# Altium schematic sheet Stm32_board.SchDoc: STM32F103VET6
size C; Organization: Protel International P/L; Address1: L3, 12a Rodborough Rd; Address2: Frenchs Forest; Address3: NSW; Address4: Australia 2086; DocumentNumber: yangjing; Revision: V1.0; SheetNumber: 0; SheetTotal: 0
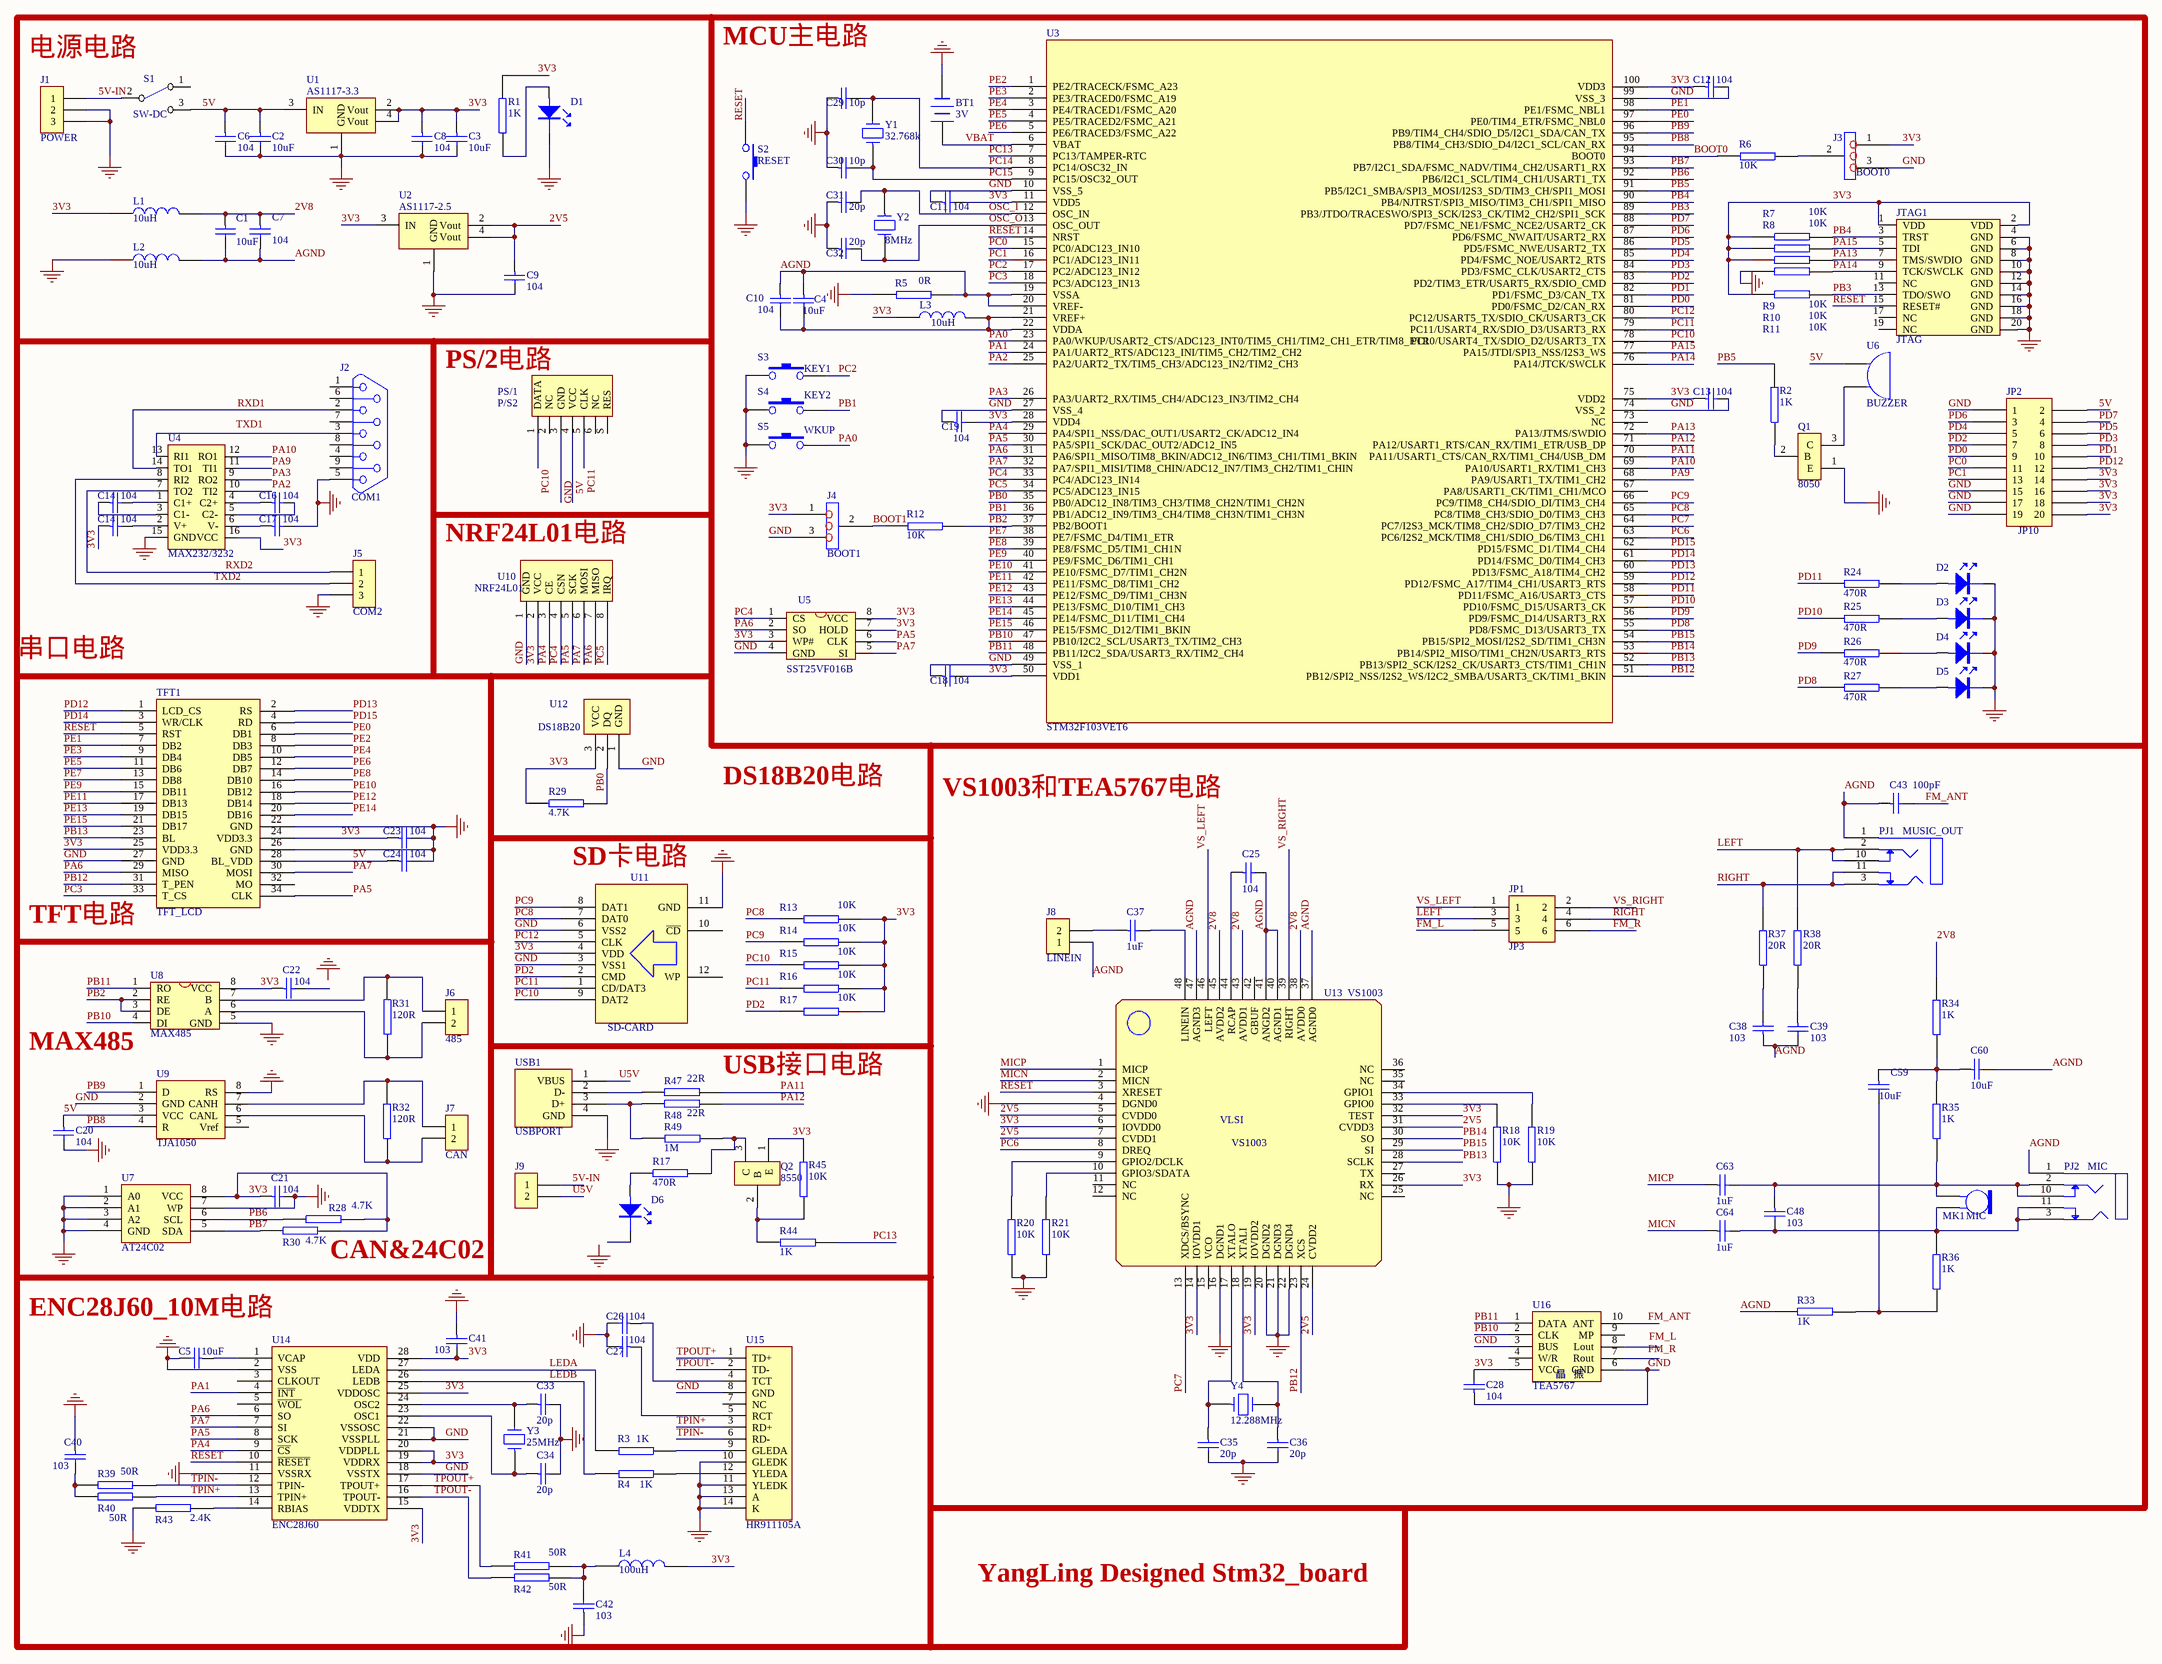
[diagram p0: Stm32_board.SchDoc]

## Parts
(Parts that share a designator on the sheet are numbered #1, #2 ... from top to bottom, then left to right.)
BT1  3V  [BAT600]
C1  10uF  [0805C]
C2  10uF  [0805C]
C3  10uF  [0805C]
C4  10uF  [0805C]
C5  10uF  [0805C]
C6  104  [0805C]
C7  104  [0805C]
C8  104  [0805C]
C9  104  [0805C]
C10  104  [0805C]
C11  104  [0805C]
C12  104  [0805C]
C13  104  [0805C]
C14#1  104  [0805C]
C14#2  104  [0805C]
C16  104  [0805C]
C17  104  [0805C]
C18  104  [0805C]
C19  104  [0805C]
C20  104  [0805C]
C21  104  [0805C]
C22  104  [0805C]
C23  104  [0805C]
C24  104  [0805C]
C25  104  [0805C]
C26  104  [0805C]
C27  104  [0805C]
C28  104  [0805C]
C29  10p  [0805C]
C30  10p  [0805C]
C31  20p  [0805C]
C32  20p  [0805C]
C33  20p  [0805C]
C34  20p  [0805C]
C35  20p  [0805C]
C36  20p  [0805C]
C37  1uF  [0805C]
C38  103  [0805C]
C39  103  [0805C]
C40  103  [0805C]
C41  103  [0805C]
C42  103  [0805C]
C43  100pF  [0805C]
C48  103  [0805C]
C59  10uF  [0805C]
C60  10uF  [0805C]
C63  1uF  [0805C]
C64  1uF  [0805C]
D1  LEDD  [0805D]  (value not drawn)
D2  LEDD  [0805D]  (value not drawn)
D3  LEDD  [0805D]  (value not drawn)
D4  LEDD  [0805D]  (value not drawn)
D5  LEDD  [0805D]  (value not drawn)
D6  LEDD  [0805D]  (value not drawn)
J1  POWER  [DC10B]
J2  COM1  [DB9_M]
J3  BOOT0  [SIP_03]
J4  BOOT1  [SIP_03]
J5  COM2  [SIP_03]
J6  485  [DC-2]
J7  CAN  [DC-2]
J8  LINEIN  [SIP_02]
J9  CON2  [SIP_02]  (value not drawn)
JP1  JP3  [JP3]
JP2  JP10  [JP10]
JTAG1  JTAG  [JTAG_20]
L1  10uH  [0805R]
L2  10uH  [0805R]
L3  10uH  [0805R]
L4  100uH  [0805R]
MK1  MIC  [SIP_02]
PJ1  MUSIC_OUT  [PJ-215-B]
PJ2  MIC  [PJ-215-B]
PS/1  P/S2  [PS2-6PIN]
Q1  8050  [SOT-23]
Q2  8550  [SOT-23]
R1  1K  [0805R]
R2  1K  [0805R]
R3  1K  [0805R]
R4  1K  [0805R]
R5  0R  [0805R]
R6  10K  [0805R]
R7  10K  [0805R]
R8  10K  [0805R]
R9  10K  [0805R]
R10  10K  [0805R]
R11  10K  [0805R]
R12  10K  [0805R]
R13  10K  [0805R]
R14  10K  [0805R]
R15  10K  [0805R]
R16  10K  [0805R]
R17#1  10K  [0805R]
R17#2  470R  [0805R]
R18  10K  [0805R]
R19  10K  [0805R]
R20  10K  [0805R]
R21  10K  [0805R]
R24  470R  [0805R]
R25  470R  [0805R]
R26  470R  [0805R]
R27  470R  [0805R]
R28  4.7K  [0805R]
R29  4.7K  [0805R]
R30  4.7K  [0805R]
R31  120R  [0805R]
R32  120R  [0805R]
R33  1K  [0805R]
R34  1K  [0805R]
R35  1K  [0805R]
R36  1K  [0805R]
R37  20R  [0805R]
R38  20R  [0805R]
R39  50R  [0805R]
R40  50R  [0805R]
R41  50R  [0805R]
R42  50R  [0805R]
R43  2.4K  [0805R]
R44  1K  [0805R]
R45  10K  [0805R]
R47  22R  [0805R]
R48  22R  [0805R]
R49  1M  [0805R]
S1  SW-DC  [SW-DC]
S2  RESET  [ANJIAN]
S3  KEY1  [ANJIAN]
S4  KEY2  [ANJIAN]
S5  WKUP  [ANJIAN]
TFT1  TFT_LCD  [LCD240320]
U1  AS1117-3.3  [AMS1117]
U2  AS1117-2.5  [ASM1117-2.5V]
U3  STM32F103VET6  [STM32F103VET6]
U4  MAX232/3232  [SOP16_MAX3232]
U5  SST25VF016B  [SOIC-8]
U6  BUZZER  [BEEP]
U7  AT24C02  [SOP-8]
U8  MAX485
U9  TJA1050  [SOP-8]
U10  NRF24L01  [NRF24L01]
U11  SD-CARD  [SDCARD_L]
U12  DS18B20  [DS18B20]
U13  VS1003  [LQFP-48]
U14  ENC28J60  [SSOP28_ENC28J60]
U15  HR911105A  [HR911105A]
U16  TEA5767  [TEA5767]
USB1  USBPORT  [USB_M]
Y1  32.768k  [XTAL_38K]
Y2  8MHz  [XTAL_12M]
Y3  25MHz  [XTAL_12M]
Y4  12.288MHz  [XTAL_12M]

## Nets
GND: BT1.2(-) C2.2 C3.2 C5.2 C6.2 C8.2 C9.2 C11.1 C12.2 C13.2 C17.2 C18.1 C19.1 C20.2 C21.2 C23.2 C24.2 C26.2 C27.2 C28.1 C29.1 C30.1 C31.1 C32.1 C33.2 C34.2 C35.2 C36.2 C40.1 C41.1 C42.1 D1.2 D2.2 D3.2 D4.2 D5.2 J1.2 J1.3 J2.5 J3.3 J4.3 J5.3 JP2.1 JP2.15 JP2.17 JP2.19 JTAG1.4(GND) JTAG1.6(GND) JTAG1.8(GND) JTAG1.10(GND) JTAG1.12(GND) JTAG1.14(GND) JTAG1.16(GND) JTAG1.18(GND) JTAG1.20(GND) L2.1 PS/1.3(GND) Q1.1(E) R5.1 R10.2 R18.1 R19.1 R20.1 R21.1 R43.2 S2.2 S3.1 S4.1 S5.1 TFT1.22(GND) TFT1.26(GND) TFT1.27(GND) U1.1(GND) U2.1(GND) U3.10(VSS_5) U3.27(VSS_4) U3.49(VSS_1) U3.74(VSS_2) U3.99(VSS_3) U4.15(GND) U5.4(GND) U7.1(A0) U7.2(A1) U7.3(A2) U7.4(GND) U7.7(WP) U8.5(GND) U9.2(GND) U9.8(RS) U10.1(GND) U11.3(VSS1) U11.6(VSS2) U11.11(GND) U12.1(GND) U13.4(DGND0) U13.16(DGND1) U13.20(DGND2) U13.21(DGND3) U13.22(DGND4) U14.2(VSS) U14.11(VSSRX) U14.18(VSSTX) U14.21(VSSPLL) U14.22(VSSOSC) U15.8(GND) U15.10(GLEDK) U15.11(YLEDK) U15.13(A) U15.14(K) U16.3(BUS) U16.6(GND) USB1.4(GND)
2V5: C9.1 U2.2(Vout) U2.4(Vout) U13.5(CVDD0) U13.7(CVDD1) U13.24(CVDD2) U13.31(CVDD3)
2V8: C1.1 C7.1 L1.2 R34.2 U13.38(AVDD0) U13.43(AVDD1) U13.45(AVDD2)
3V3: C3.1 C8.1 C11.2 C12.1 C13.1 C14#2.1 C18.2 C19.2 C21.1 C22.1 C23.1 C28.2 C41.2 J3.1 J4.1 JP2.14 JP2.16 JP2.18 JP2.20 JTAG1.1(VDD) JTAG1.2(VDD) L1.1 L3.1 L4.2 Q2.1(E) R1.2 R7.2 R8.2 R9.2 R11.2 R13.2 R14.2 R15.2 R16.2 R17#1.2 R28.1 R29.2 R30.1 R45.2 TFT1.24(VDD3.3) TFT1.25(VDD3.3) U1.2(Vout) U1.4(Vout) U2.3(IN) U3.11(VDD5) U3.28(VDD4) U3.50(VDD1) U3.75(VDD2) U3.100(VDD3) U4.16(VCC) U5.3(WP#) U5.7(HOLD) U5.8(VCC) U7.8(VCC) U8.8(VCC) U10.2(VCC) U11.4(VDD) U12.3(VCC) U13.6(IOVDD0) U13.14(IOVDD1) U13.19(IOVDD2) U13.26(RX) U13.32(TEST) U14.15(VDDTX) U14.19(VDDRX) U14.20(VDDPLL) U14.25(VDDOSC) U14.28(VDD) U16.5(VCC)
5V: C2.1 C6.1 C20.1 C24.1 JP2.2 PS/1.4(VCC) S1.3(NO) TFT1.28(BL_VDD) U1.3(IN) U6.1(A) U9.3(VCC)
5V-IN: J1.1 J9.1 S1.2(COMMON)
AGND: C1.2 C4.1 C7.2 C10.1 C25.2 C38.1 C39.2 C43.1 C60.2 J8.1 L2.2 PJ1.1 PJ2.1 R5.2 R33.2 U3.19(VSSA) U3.20(VREF-) U13.37(AGND0) U13.40(AGND1) U13.41(ANGD2) U13.47(AGND3)
BOOT0: R6.1 U3.94(BOOT0)
BOOT1: J4.2 R12.1
FM_ANT: C43.2 U16.10(ANT)
FM_L: JP1.5
FM_R: JP1.6
LEDA: R3.1 U14.27(LEDA)
LEDB: R4.1 U14.26(LEDB)
LEFT: JP1.3 PJ1.2 PJ1.10 R38.2
MICN: C64.1 U13.2(MICN)
MICP: C63.1 U13.1(MICP)
OSC_I: C31.2 U3.12(OSC_IN) Y2.1
OSC_O: C32.2 U3.13(OSC_OUT) Y2.2
PA0: S5.2 U3.23(PA0/WKUP/USART2_CTS/ADC123_INT0/TIM5_CH1/TIM2_CH1_ETR/TIM8_ETR)
PA1: U3.24(PA1/UART2_RTS/ADC123_INI/TIM5_CH2/TIM2_CH2) U14.4(~{INT})
PA2: U3.25(PA2/UART2_TX/TIM5_CH3/ADC123_IN2/TIM2_CH3) U4.10(TI2)
PA3: U3.26(PA3/UART2_RX/TIM5_CH4/ADC123_IN3/TIM2_CH4) U4.9(RO2)
PA4: U3.29(PA4/SPI1_NSS/DAC_OUT1/USART2_CK/ADC12_IN4) U10.3(CE) U14.9(~{CS})
PA5: TFT1.34(CLK) U3.30(PA5/SPI1_SCK/DAC_OUT2/ADC12_IN5) U5.6(CLK) U10.5(SCK) U14.8(SCK)
PA6: TFT1.29(MISO) U3.31(PA6/SPI1_MISO/TIM8_BKIN/ADC12_IN6/TIM3_CH1/TIM1_BKIN) U5.2(SO) U10.7(MISO) U14.6(SO)
PA7: TFT1.30(MOSI) U3.32(PA7/SPI1_MISI/TIM8_CHIN/ADC12_IN7/TIM3_CH2/TIM1_CHIN) U5.5(SI) U10.6(MOSI) U14.7(SI)
PA9: U3.68(PA9/USART1_TX/TIM1_CH2) U4.11(TI1)
PA10: U3.69(PA10/USART1_RX/TIM1_CH3) U4.12(RO1)
PA11: R47.1 U3.70(PA11/USART1_CTS/CAN_RX/TIM1_CH4/USB_DM)
PA12: R48.1 U3.71(PA12/USART1_RTS/CAN_RX/TIM1_ETR/USB_DP)
PA13: JTAG1.7(TMS/SWDIO) R9.1 U3.72(PA13/JTMS/SWDIO)
PA14: JTAG1.9(TCK/SWCLK) R10.1 U3.76(PA14/JTCK/SWCLK)
PA15: JTAG1.5(TDI) R8.1 U3.77(PA15/JTDI/SPI3_NSS/I2S3_WS)
PB0: R29.1 U3.35(PB0/ADC12_IN8/TIM3_CH3/TIM8_CH2N/TIM1_CH2N) U12.2(DQ)
PB1: S4.2 U3.36(PB1/ADC12_IN9/TIM3_CH4/TIM8_CH3N/TIM1_CH3N)
PB2: R12.2 U3.37(PB2/BOOT1) U8.2(RE) U8.3(DE)
PB3: JTAG1.13(TDO/SWO) R11.1 U3.89(PB3/JTDO/TRACESWO/SPI3_SCK/I2S3_CK/TIM2_CH2/SPI1_SCK)
PB4: JTAG1.3(TRST) R7.1 U3.90(PB4/NJTRST/SPI3_MISO/TIM3_CH1/SPI1_MISO)
PB5: R2.2 U3.91(PB5/I2C1_SMBA/SPI3_MOSI/I2S3_SD/TIM3_CH/SPI1_MOSI)
PB6: R28.2 U3.92(PB6/I2C1_SCL/TIM4_CH1/USART1_TX) U7.6(SCL)
PB7: R30.2 U3.93(PB7/I2C1_SDA/FSMC_NADV/TIM4_CH2/USART1_RX) U7.5(SDA)
PB8: U3.95(PB8/TIM4_CH3/SDIO_D4/I2C1_SCL/CAN_RX) U9.4(R)
PB9: U3.96(PB9/TIM4_CH4/SDIO_D5/I2C1_SDA/CAN_TX) U9.1(D)
PB10: U3.47(PB10/I2C2_SCL/USART3_TX/TIM2_CH3) U8.4(DI) U16.2(CLK)
PB11: U3.48(PB11/I2C2_SDA/USART3_RX/TIM2_CH4) U8.1(RO) U16.1(DATA)
PB12: TFT1.31(T_PEN) U3.51(PB12/SPI2_NSS/I2S2_WS/I2C2_SMBA/USART3_CK/TIM1_BKIN) U13.23(XCS)
PB13: TFT1.23(BL) U3.52(PB13/SPI2_SCK/I2S2_CK/USART3_CTS/TIM1_CH1N) U13.28(SCLK)
PB14: U3.53(PB14/SPI2_MISO/TIM1_CH2N/USART3_RTS) U13.30(SO)
PB15: U3.54(PB15/SPI2_MOSI/I2S2_SD/TIM1_CH3N) U13.29(SI)
PC0: JP2.11 U3.15(PC0/ADC123_IN10)
PC1: JP2.13 U3.16(PC1/ADC123_IN11)
PC2: S3.2 U3.17(PC2/ADC123_IN12)
PC3: TFT1.33(T_CS) U3.18(PC3/ADC123_IN13)
PC4: U3.33(PC4/ADC123_IN14) U5.1(CS) U10.4(CSN)
PC5: U3.34(PC5/ADC123_IN15) U10.8(IRQ)
PC6: U3.63(PC6/I2S2_MCK/TIM8_CH1/SDIO_D6/TIM3_CH1) U13.8(DREQ)
PC7: U3.64(PC7/I2S3_MCK/TIM8_CH2/SDIO_D7/TIM3_CH2) U13.13(XDCS/BSYNC)
PC8: R13.1 U3.65(PC8/TIM8_CH3/SDIO_D0/TIM3_CH3) U11.7(DAT0)
PC9: R14.1 U3.66(PC9/TIM8_CH4/SDIO_DI/TIM3_CH4) U11.8(DAT1)
PC10: PS/1.1(DATA) R15.1 U3.78(PC10/USART4_TX/SDIO_D2/USART3_TX) U11.9(DAT2)
PC11: PS/1.5(CLK) R16.1 U3.79(PC11/USART4_RX/SDIO_D3/USART3_RX) U11.1(CD/DAT3)
PC12: U3.80(PC12/USART5_TX/SDIO_CK/USART3_CK) U11.5(CLK)
PC13: R44.2 U3.7(PC13/TAMPER-RTC)
PC14: C29.2 U3.8(PC14/OSC32_IN) Y1.2
PC15: C30.2 U3.9(PC15/OSC32_OUT) Y1.1
PD0: JP2.9 U3.81(PD0/FSMC_D2/CAN_RX)
PD1: JP2.10 U3.82(PD1/FSMC_D3/CAN_TX)
PD2: JP2.7 R17#1.1 U3.83(PD2/TIM3_ETR/USART5_RX/SDIO_CMD) U11.2(CMD)
PD3: JP2.8 U3.84(PD3/FSMC_CLK/USART2_CTS)
PD4: JP2.5 U3.85(PD4/FSMC_NOE/USART2_RTS)
PD5: JP2.6 U3.86(PD5/FSMC_NWE/USART2_TX)
PD6: JP2.3 U3.87(PD6/FSMC_NWAIT/USART2_RX)
PD7: JP2.4 U3.88(PD7/FSMC_NE1/FSMC_NCE2/USART2_CK)
PD8: R27.1 U3.55(PD8/FSMC_D13/USART3_TX)
PD9: R26.1 U3.56(PD9/FSMC_D14/USART3_RX)
PD10: R25.1 U3.57(PD10/FSMC_D15/USART3_CK)
PD11: R24.1 U3.58(PD11/FSMC_A16/USART3_CTS)
PD12: JP2.12 TFT1.1(LCD_CS) U3.59(PD12/FSMC_A17/TIM4_CH1/USART3_RTS)
PD13: TFT1.2(RS) U3.60(PD13/FSMC_A18/TIM4_CH2)
PD14: TFT1.3(WR/CLK) U3.61(PD14/FSMC_D0/TIM4_CH3)
PD15: TFT1.4(RD) U3.62(PD15/FSMC_D1/TIM4_CH4)
PE0: TFT1.6(DB1) U3.97(PE0/TIM4_ETR/FSMC_NBL0)
PE1: TFT1.7(DB2) U3.98(PE1/FSMC_NBL1)
PE2: TFT1.8(DB3) U3.1(PE2/TRACECK/FSMC_A23)
PE3: TFT1.9(DB4) U3.2(PE3/TRACED0/FSMC_A19)
PE4: TFT1.10(DB5) U3.3(PE4/TRACED1/FSMC_A20)
PE5: TFT1.11(DB6) U3.4(PE5/TRACED2/FSMC_A21)
PE6: TFT1.12(DB7) U3.5(PE6/TRACED3/FSMC_A22)
PE7: TFT1.13(DB8) U3.38(PE7/FSMC_D4/TIM1_ETR)
PE8: TFT1.14(DB10) U3.39(PE8/FSMC_D5/TIM1_CH1N)
PE9: TFT1.15(DB11) U3.40(PE9/FSMC_D6/TIM1_CH1)
PE10: TFT1.16(DB12) U3.41(PE10/FSMC_D7/TIM1_CH2N)
PE11: TFT1.17(DB13) U3.42(PE11/FSMC_D8/TIM1_CH2)
PE12: TFT1.18(DB14) U3.43(PE12/FSMC_D9/TIM1_CH3N)
PE13: TFT1.19(DB15) U3.44(PE13/FSMC_D10/TIM1_CH3)
PE14: TFT1.20(DB16) U3.45(PE14/FSMC_D11/TIM1_CH4)
PE15: TFT1.21(DB17) U3.46(PE15/FSMC_D12/TIM1_BKIN)
RESET: JTAG1.15(RESET#) S2.1 TFT1.5(RST) U3.14(NRST) U13.3(XRESET) U14.10(~{RESET})
RIGHT: JP1.4 PJ1.3 PJ1.11 R37.2
RXD1: J2.2 U4.14(TO1)
RXD2: J5.1 U4.7(TO2)
TPIN+: R40.1 U14.13(TPIN+) U15.3(RD+)
TPIN-: R39.1 U14.12(TPIN-) U15.6(RD-)
TPOUT+: R41.2 U14.17(TPOUT+) U15.1(TD+)
TPOUT-: R42.2 U14.16(TPOUT-) U15.2(TD-)
TXD2: J5.2 U4.8(RI2)
U5V: J9.2 USB1.1(VBUS)
VBAT: BT1.1(+) U3.6(VBAT)
VS_LEFT: JP1.1 U13.46(LEFT)
VS_RIGHT: JP1.2 U13.39(RIGHT)
NetC4_2: C4.2 C10.2 L3.2 U3.21(VREF+) U3.22(VDDA)
NetC5_1: C5.1 U14.1(VCAP)
NetC14#1_1: C14#1.1 U4.3(C1-)
NetC14#1_2: C14#1.2 U4.1(C1+)
NetC14#2_2: C14#2.2 U4.2(V+)
NetC16_1: C16.1 U4.4(C2+)
NetC16_2: C16.2 U4.5(C2-)
NetC17_1: C17.1 U4.6(V-)
NetC25_1: C25.1 U13.44(RCAP)
NetC26_1: C26.1 U15.4(TCT)
NetC27_1: C27.1 U15.5(RCT)
NetC33_1: C33.1 U14.24(OSC2) Y3.2
NetC34_1: C34.1 U14.23(OSC1) Y3.1
NetC35_1: C35.1 U13.17(XTALO) Y4.1
NetC36_1: C36.1 U13.18(XTALI) Y4.2
NetC37_1: C37.1 J8.2
NetC37_2: C37.2 U13.48(LINEIN)
NetC38_2: C38.2 R37.1
NetC39_1: C39.1 R38.1
NetC40_2: C40.2 R39.2 R40.2
NetC42_2: C42.2 L4.1 R41.1 R42.1
NetC48_1: C48.1 C63.2 MK1.1 PJ2.2 PJ2.10 R35.1
NetC48_2: C48.2 C64.2 MK1.2 PJ2.3 PJ2.11 R36.2
NetC59_1: C59.1 C60.1 R34.1 R35.2
NetC59_2: C59.2 R33.1 R36.1
NetD1_1: D1.1 R1.1
NetD2_1: D2.1 R24.2
NetD3_1: D3.1 R25.2
NetD4_1: D4.1 R26.2
NetD5_1: D5.1 R27.2
NetD6_1: D6.1 R17#2.2
NetJ2_3: J2.3 U4.13(RI1)
NetJ3_2: J3.2 R6.2
NetJ6_1: J6.1 R31.1 U8.7(B)
NetJ6_2: J6.2 R31.2 U8.6(A)
NetJ7_1: J7.1 R32.2 U9.7(CANH)
NetJ7_2: J7.2 R32.1 U9.6(CANL)
NetQ1_2: Q1.2(B) R2.1
NetQ1_3: Q1.3(C) U6.2(B)
NetQ2_2: Q2.2(B) R44.1 R45.1
NetQ2_3: Q2.3(C) R17#2.1 R49.2
NetR3_2: R3.2 U15.9(GLEDA)
NetR4_2: R4.2 U15.12(YLEDA)
NetR18_2: R18.2 U13.33(GPIO0)
NetR19_2: R19.2 U13.34(GPIO1)
NetR20_2: R20.2 U13.9(GPIO2/DCLK)
NetR21_2: R21.2 U13.10(GPIO3/SDATA)
NetR43_1: R43.1 U14.14(RBIAS)
NetR47_2: R47.2 USB1.2(D-)
NetR48_2: R48.2 R49.1 USB1.3(D+)

Not connected (* = marked no-connect by the designer): C22 2; D6 2; J2 1 4 6 7 8 9; JTAG1 11(NC) 17(NC) 19(NC); PS/1 2(NC) 6(NC) S(RES); S1 1(OFF); TFT1 32(MO); U3 67(PA8/USART1_CK/TIM1_CH1/MCO) 73(NC); U9 5(Vref); U11 10(~{CD}) 12(WP); U13 11(NC) 12(NC) 15(VCO) 25(NC) 27(TX) 35(NC) 36(NC) 42(GBUF); U14 3(CLKOUT) 5(~{WOL}); U15 7(NC); U16 4(W/R) 7(Rout) 8(Lout) 9(MP)

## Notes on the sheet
- MCU主电路
- (near J1) 电源电路
- PS/2电路
- NRF24L01电路
- 串口电路
- DS18B20电路
- VS1003和TEA5767电路
- SD卡电路
- TFT电路
- MAX485
- USB接口电路
- CAN&24C02
- (near C5) ENC28J60_10M电路
- YangLing Designed Stm32_board
- Labels drawn without touching a wire or pin: FM_L, FM_R, GND, TXD1

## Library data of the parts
BT1 = BATTERY
C1-C13 C14#1 C14#2 C16-C43 C48 C59 C60 C63 C64 = CAP: Capacitor
J1 J5 = CON3: Connector
J2 = DB9
J3 J4 = BOOT
J6-J9 = CON2: Connector
L1-L4 = INDUCTOR
MK1 = MICROPHONE2: Microphone
PJ1 PJ2 = PJ-215-B
R1-R16 R17#1 R17#2 R18-R21 R24-R45 R47-R49 = RES2
S2-S5 = SW-PB
U2 = AS1117-3.3
U3 = STM32F103VET6: STM32 ARM-based 32-bit MCU with 256 Kbytes Flash, 64-pin LQFP, Industrial Temperature
U5 = SST25VF016B: W25X16;SST25VF016;MX25L1605
U7 = AT24C02: 串行2K IIC EEPROM (256*8)
USB1 = USBPORT: Text Field1: 50
Y1-Y4 = CRYSTAL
